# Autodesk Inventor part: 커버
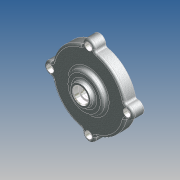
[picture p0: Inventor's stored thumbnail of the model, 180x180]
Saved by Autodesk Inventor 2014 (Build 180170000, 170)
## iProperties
Company: 한국ATC센터
Created: 2012-05
Part Number: 커버
Document SubType Name: 모델링
Designer: KYOUNG IL JANG
Mass: 196.657 g
Surface Area: 278.607 cm^2
Volume: 72.5671 cm^3
Density: 2.71 g/cm^3
Material: 알루미늄-6061
Appearance: 알루미늄 캐스트
변환 표준: STEP AP214IS
파일 이름: C:\Users\SeoGD\Desktop\?쒗뿕\而ㅻ쾭-1.stp
전처리기: Build: 253, Release: 2010 SP1 - Date: Wed 07/29/2009
전송 단위: 밀리미터
불확실성: 0.01
Author: KYOUNG IL JANG
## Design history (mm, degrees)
sketch "스케치1"
  geometry: L1 (0, 0)-(0, 26); L2 (50, 0)-(50, 15); L3 (50, 15)-(25, 15); L4 (25, 15)-(25, 21); L5 (25, 21)-(15, 21); L6 (15, 21)-(13.66, 26); L7 (13.66, 26)-(10, 26); L8 (50, 0)-(45, 0); L9 (45, 0)-(45, 10); L10 (45, 10)-(14.5, 10); L11 (14.5, 10)-(13.266, 3); L12 (13.266, 3)-(11, 3); L13 (11, 3)-(11, 16); L14 (11, 16)-(7.5, 16); L15 (7.5, 16)-(7.5, 19); L16 (7.5, 19)-(10, 19); L17 (10, 19)-(10, 26)
  constraints: 34 end point, 10 parallel, 2 perpendicular, 2 point on line, 1 vertical
  dimensions: "d11" = 100 diameter of L2 L1; "d12" = 22 diameter of L13 L1; "d13" = 90 diameter of L9 L1; "d14" = 15 distance between parallel lines of L3 L8; "d15" = 10 distance between parallel lines of L8 L10; "d16" = 29 diameter of L10.end L1; "d17" = 100 deg angle of L11 L10; "d18" = 7 distance between parallel lines of L12 L10; "d19" = 13 distance between parallel lines of L14 L12; "d20" = 3 distance between parallel lines of L16 L14; "d21" = 15 diameter of L15 L1; "d22" = 20 diameter of L17 L1; "d23" = 30 diameter of L5.end L1; "d24" = 6 distance between parallel lines of L5 L3; "d25" = 50 diameter of L4 L1; "d26" = 105 deg angle of L5 L6; "d50" = 26 distance of L1.start L1.end
revolve "회전1" sketch "스케치1" stored, may be unused: angle "d27" = 90 deg
sketch "스케치2" dims "d29" = 104
  geometry: A1 r 8.5 centre (0, 52) between (8.074, 49.344) and (-8.074, 49.344); A2 r 50 centre (0, 0) between (-8.074, 49.344) and (8.074, 49.344) reference; 2 further points
  constraints: 4 point on circle, 2 vertical alignment, 1 centre point, 1 coincident, 2 other
  dimensions: "d28" = 17 diameter of A1
extrude "돌출1" join sketch "스케치2" stored distance "d30" = 10; taper "d31" = 0 deg
fillet "모깎기3" dims "d32" = 3
fillet "모깎기4" dims "d45" = 3, "d46" = 0.2
chamfer "모따기1" distance "d47" = 1; stored, may be unused: second distance "d48" = 2, angle "d49" = 45 deg
hole "구멍2" diameter "d38" = 5.5; stored, may be unused: countersink angle "d42" = 90 deg, drill point angle "d44" = 118 deg; dims "d36" = 10, "d37" = 10, "d39" = 6, "d40" = 9.5, "d41" = 5.4, "d43" = 8
node "솔리드1"
node "솔리드 본체"
node "곡면 본체"
pattern_circular "원형 패턴1" dims angle "d34" = 360 deg
pattern_circular "원형 패턴2" dims angle "d52" = 360 deg
node "솔리드2"
